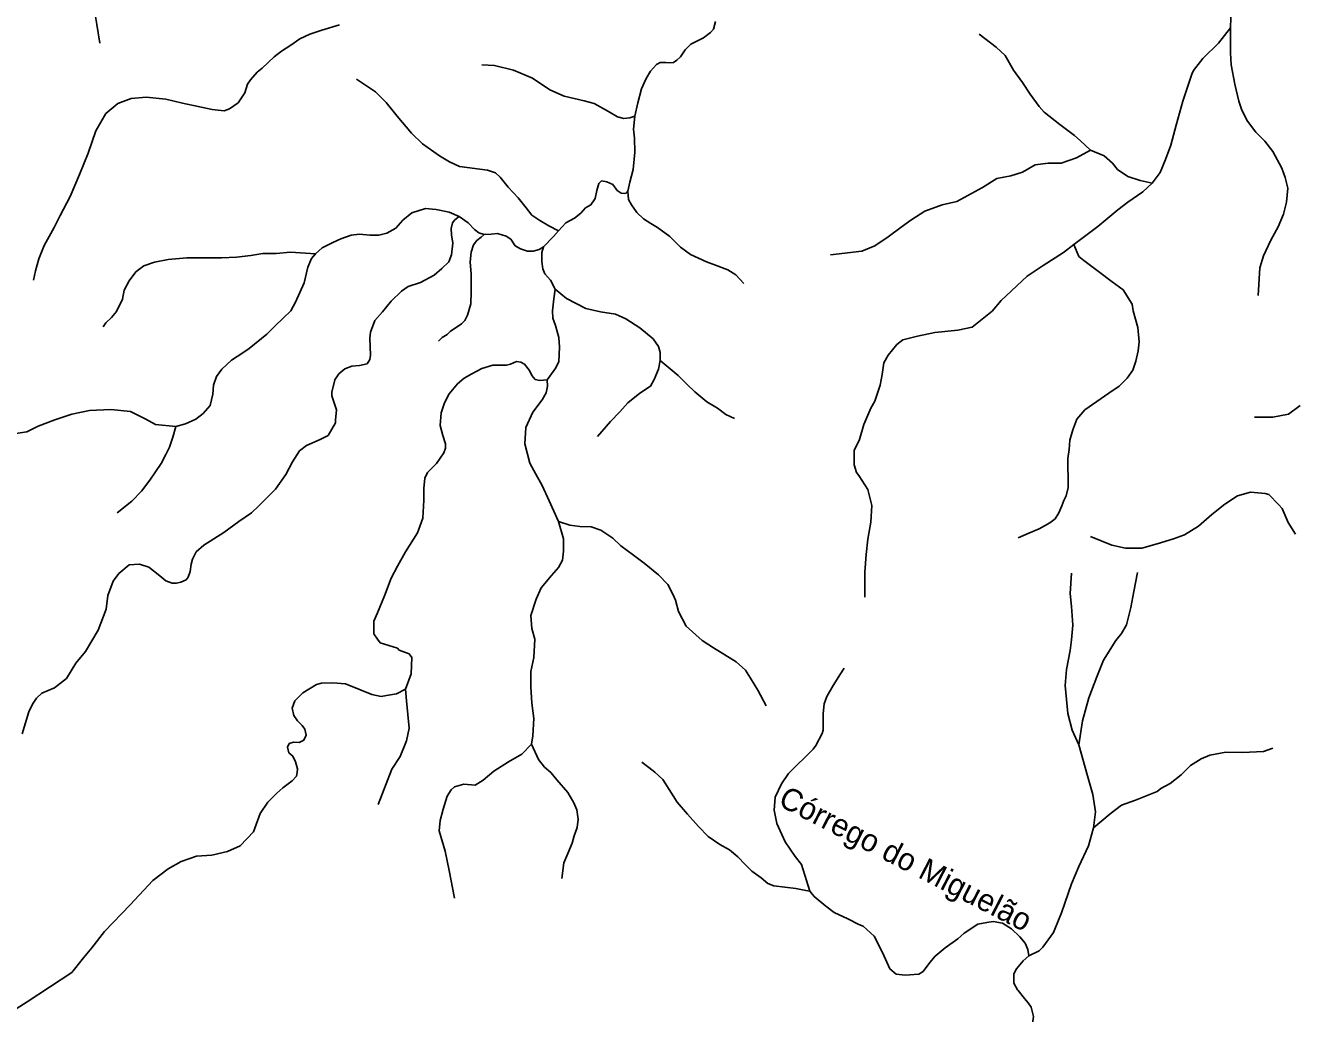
# Model space of a CAD drawing. Extents: x 436.3 to 500.4, y 8231 to 8286.4.
# Drawn here: x 456.78 to 465.31, y 8261.09 to 8267.74 of the extents above; entities that cross this region are included whole.
import ezdxf

# ---------------------------------------------------------------- set-up
doc = ezdxf.new("R2010")
doc.units = 0
doc.header["$LTSCALE"] = 0.08
doc.linetypes.add('LONG_DASHED', pattern=[7.5, 6, -1.5])
doc.layers.add('61', color=7, linetype='Continuous')
doc.layers.add('9', color=7, linetype='LONG_DASHED', lineweight=25)

msp = doc.modelspace()

# ---------------------------------------------------------------- linework, layer by layer
at = {"layer": '9'}
for points in [[(457.2814, 8267.6213), (457.2633, 8267.7468), (457.2498, 8267.8274), (457.2318, 8267.9082), (457.2093, 8268.1056), (457.1867, 8268.2042), (457.1732, 8268.2671), (457.1777, 8268.3343), (457.1957, 8268.4062), (457.2362, 8268.5453), (457.2497, 8268.6082), (457.2451, 8268.6844), (457.2361, 8268.7473), (457.1956, 8268.8372), (457.1595, 8268.9135), (457.1053, 8269.0054), (457.0783, 8269.0818), (457.0468, 8269.1671), (457.0287, 8269.2526), (457.0287, 8269.3694), (457.03, 8269.4566)], [(464.8947, 8267.7236), (464.8968, 8267.7915), (464.9249, 8267.9547), (464.9529, 8268.074), (464.9928, 8268.1576), (465.0567, 8268.2651), (465.1087, 8268.3568), (465.185, 8268.4466)], [(460.8851, 8267.1303), (460.9041, 8267.2198), (460.9298, 8267.3138), (460.9614, 8267.3834), (460.99, 8267.4318), (461.0299, 8267.4774), (461.0557, 8267.4917), (461.0928, 8267.4918), (461.1185, 8267.4889), (461.1442, 8267.4918), (461.167, 8267.506), (461.1928, 8267.5288), (461.2242, 8267.5773), (461.2613, 8267.6144), (461.347, 8267.6572), (461.393, 8267.6927), (461.413, 8267.7155), (461.4274, 8267.7668)], [(456.8355, 8266.026), (456.849, 8266.0887), (456.8715, 8266.1692), (456.9074, 8266.2588), (456.975, 8266.3796), (457.0154, 8266.4603), (457.0829, 8266.59), (457.146, 8266.7378), (457.2044, 8266.8811), (457.2549, 8267.0304), (457.3224, 8267.1469), (457.4035, 8267.2142), (457.4938, 8267.2491), (457.594, 8267.2585), (457.7274, 8267.2452), (457.8399, 8267.2183), (457.9435, 8267.1958), (458.0385, 8267.1741), (458.1195, 8267.1651), (458.1555, 8267.1784), (458.214, 8267.2188), (458.259, 8267.286), (458.277, 8267.3444), (458.2972, 8267.3739), (458.3411, 8267.4261), (458.376, 8267.4519), (458.457, 8267.5281), (458.5065, 8267.5684), (458.5695, 8267.6088), (458.628, 8267.6492), (458.6971, 8267.6813), (458.7781, 8267.7082), (458.8951, 8267.7441)], [(463.2016, 8267.682), (463.3181, 8267.5937), (463.3787, 8267.5379), (463.4345, 8267.4402), (463.4951, 8267.3565), (463.5464, 8267.2774), (463.6069, 8267.1937), (463.6395, 8267.1565), (463.7467, 8267.0729), (463.8446, 8266.9985), (463.8818, 8266.9659), (463.9528, 8266.9006)], [(464.3685, 8266.6777), (464.4215, 8266.7506), (464.4574, 8266.838), (464.4933, 8266.9335), (464.5293, 8267.0687), (464.5733, 8267.2317), (464.6334, 8267.4135), (464.6454, 8267.4374), (464.7092, 8267.517), (464.813, 8267.6204), (464.8947, 8267.7236)], [(465.0805, 8265.9223), (465.0928, 8266.1091), (465.1173, 8266.1903), (465.1662, 8266.2959), (465.2151, 8266.3852), (465.2518, 8266.4705), (465.2722, 8266.5518), (465.2804, 8266.6451), (465.2639, 8266.7159), (465.2399, 8266.7792), (465.1789, 8266.8929), (465.1261, 8266.962), (465.0652, 8267.0229), (465.0083, 8267.096), (464.9717, 8267.1691), (464.9512, 8267.2311), (464.9229, 8267.3449), (464.8986, 8267.4749), (464.8945, 8267.557), (464.8947, 8267.7236)], [(459.8554, 8267.4759), (459.9406, 8267.47), (460.0683, 8267.4397), (460.1961, 8267.3852), (460.3116, 8267.3065), (460.4089, 8267.2641), (460.5427, 8267.2339), (460.6096, 8267.2158), (460.7069, 8267.1614), (460.7677, 8267.125), (460.8103, 8267.113), (460.8515, 8267.1185), (460.8851, 8267.1303)], [(459.0101, 8267.3789), (459.1377, 8267.294), (459.2107, 8267.2213), (459.2838, 8267.1304), (459.381, 8267.0152), (459.454, 8266.9425), (459.5695, 8266.8638), (459.6365, 8266.8214), (459.7034, 8266.7911), (459.8919, 8266.7669), (459.9466, 8266.7487), (459.977, 8266.7185), (460.0318, 8266.6518), (460.0986, 8266.5792), (460.1534, 8266.5125), (460.1899, 8266.4641), (460.2445, 8266.4277), (460.3054, 8266.3915), (460.3698, 8266.358)], [(460.8383, 8266.6251), (460.8498, 8266.6848), (460.8726, 8266.7702), (460.884, 8266.8868), (460.8812, 8266.9807), (460.8756, 8267.0433), (460.8851, 8267.1303)], [(462.2021, 8266.1965), (462.412, 8266.2201), (462.5006, 8266.2575), (462.5893, 8266.318), (462.678, 8266.3832), (462.7433, 8266.4298), (462.8367, 8266.4904), (462.9534, 8266.5324), (463.0513, 8266.5558), (463.224, 8266.649), (463.322, 8266.7096), (463.4153, 8266.7282), (463.4945, 8266.7517), (463.5786, 8266.8029), (463.6672, 8266.8123), (463.7557, 8266.8123), (463.8584, 8266.8496), (463.9528, 8266.9006)], [(463.9528, 8266.9006), (464.045, 8266.8637), (464.1009, 8266.8126), (464.1335, 8266.7707), (464.2033, 8266.7243), (464.2873, 8266.6964), (464.3685, 8266.6777)], [(460.3698, 8266.358), (460.42, 8266.4118), (460.4775, 8266.444), (460.5207, 8266.4762), (460.553, 8266.5121), (460.589, 8266.5335), (460.6177, 8266.5765), (460.6285, 8266.6302), (460.6429, 8266.6767), (460.6608, 8266.6947), (460.6967, 8266.6876), (460.7362, 8266.6696), (460.765, 8266.6303), (460.7926, 8266.6108), (460.8126, 8266.608), (460.8269, 8266.6108), (460.8383, 8266.6251)], [(463.8405, 8266.2653), (464.0012, 8266.3867), (464.1368, 8266.4981), (464.2046, 8266.5498), (464.3043, 8266.6213), (464.3685, 8266.6777)], [(461.6189, 8266.0042), (461.5634, 8266.0627), (461.5112, 8266.0952), (461.4264, 8266.1276), (461.3676, 8266.1502), (461.2599, 8266.199), (461.1913, 8266.2476), (461.1195, 8266.3192), (461.0379, 8266.3809), (460.9922, 8266.4069), (460.9433, 8266.4393), (460.8976, 8266.4817), (460.8616, 8266.5337), (460.842, 8266.5694), (460.8383, 8266.6251)], [(458.7334, 8266.2036), (458.7801, 8266.2429), (458.852, 8266.2786), (458.9058, 8266.3036), (458.9741, 8266.3287), (459.0315, 8266.3357), (459.0998, 8266.3286), (459.1609, 8266.3286), (459.2147, 8266.3428), (459.2758, 8266.375), (459.3225, 8266.4287), (459.382, 8266.4795), (459.4755, 8266.5081), (459.5472, 8266.5009), (459.6335, 8266.4831), (459.7018, 8266.4544)], [(459.7018, 8266.4544), (459.673, 8266.4312), (459.6569, 8266.4118), (459.6472, 8266.3733), (459.6504, 8266.3317), (459.6601, 8266.2739), (459.6504, 8266.1969), (459.6311, 8266.1488), (459.586, 8266.1038), (459.5344, 8266.0589), (459.441, 8266.0109), (459.3573, 8265.982), (459.313, 8265.952), (459.2439, 8265.8833), (459.186, 8265.8124), (459.1341, 8265.7552), (459.1053, 8265.6749), (459.0996, 8265.6348), (459.1053, 8265.5202), (459.0996, 8265.4915), (459.0824, 8265.4629), (459.0306, 8265.4514), (458.9788, 8265.4457), (458.9328, 8265.4286), (458.8925, 8265.3942), (458.8637, 8265.3541), (458.8436, 8265.2723), (458.8436, 8265.2473), (458.8752, 8265.1534), (458.8682, 8265.0831), (458.8682, 8265.0659), (458.8192, 8264.9809), (458.7667, 8264.952), (458.6746, 8264.9121), (458.6266, 8264.8769), (458.5805, 8264.8024), (458.5346, 8264.7165), (458.4655, 8264.6191), (458.3504, 8264.5045), (458.3043, 8264.4587), (458.218, 8264.4015), (458.118, 8264.326), (457.9831, 8264.2414), (457.9312, 8264.196), (457.9063, 8264.1483), (457.898, 8264.1132), (457.8897, 8264.0636), (457.8763, 8264.0258), (457.8638, 8264.0093), (457.8275, 8263.9932), (457.7984, 8263.985), (457.7693, 8263.9851), (457.7277, 8264.0017), (457.6862, 8264.035), (457.6116, 8264.0932), (457.549, 8264.1139), (457.4802, 8264.109), (457.4112, 8264.0518), (457.3728, 8263.9986), (457.3364, 8263.9027), (457.325, 8263.8109), (457.2715, 8263.6704), (457.1851, 8263.527), (457.1218, 8263.4468), (457.0585, 8263.3434), (456.978, 8263.2805), (456.8916, 8263.2462), (456.8571, 8263.2118), (456.8283, 8263.1716), (456.8053, 8263.1198), (456.7881, 8263.0682), (456.7593, 8262.9705)], [(459.7018, 8266.4544), (459.7628, 8266.4115), (459.8052, 8266.3672), (459.8343, 8266.3448), (459.8708, 8266.3325)], [(459.5617, 8265.6152), (459.5871, 8265.6406), (459.6199, 8265.6588), (459.6417, 8265.6805), (459.718, 8265.7312), (459.7399, 8265.7534), (459.7581, 8265.7897), (459.78, 8265.8658), (459.7836, 8265.9455), (459.7836, 8266.065), (459.7763, 8266.1485), (459.7836, 8266.2137), (459.7982, 8266.2644), (459.82, 8266.2934), (459.8491, 8266.3151), (459.8708, 8266.3325)], [(459.8708, 8266.3325), (459.9172, 8266.3364), (459.9603, 8266.34), (460.0178, 8266.3221), (460.0501, 8266.3006), (460.0788, 8266.2577), (460.1148, 8266.2363), (460.1615, 8266.2219), (460.201, 8266.2219), (460.2405, 8266.2327), (460.2706, 8266.2496)], [(460.2706, 8266.2496), (460.3375, 8266.3186), (460.3698, 8266.358)], [(460.347, 8265.9655), (460.316, 8266.0261), (460.2791, 8266.0685), (460.2649, 8266.1025), (460.2592, 8266.1506), (460.2592, 8266.2128), (460.2706, 8266.2496)], [(462.4332, 8263.8924), (462.4332, 8264.0595), (462.4412, 8264.1788), (462.4532, 8264.2822), (462.473, 8264.3976), (462.481, 8264.5089), (462.4532, 8264.6162), (462.3934, 8264.7116), (462.3775, 8264.7314), (462.3615, 8264.783), (462.3615, 8264.8784), (462.3974, 8264.954), (462.4253, 8265.0534), (462.4732, 8265.1632), (462.5011, 8265.2109), (462.537, 8265.3182), (462.549, 8265.3898), (462.561, 8265.4693), (462.5889, 8265.521), (462.6487, 8265.5926), (462.6886, 8265.6244), (462.7882, 8265.6484), (462.9038, 8265.6724), (463.0592, 8265.6886), (463.1549, 8265.7085), (463.2905, 8265.8159), (463.3514, 8265.8895), (463.5268, 8266.0526), (463.6344, 8266.1242), (463.77, 8266.2118), (463.8405, 8266.2653)], [(463.4663, 8264.2912), (463.5368, 8264.3215), (463.6074, 8264.3517), (463.678, 8264.3921), (463.7149, 8264.419), (463.7385, 8264.4592), (463.7587, 8264.5062), (463.7721, 8264.5431), (463.7889, 8264.5732), (463.8023, 8264.6302), (463.8023, 8264.7039), (463.7991, 8264.7609), (463.7991, 8264.8246), (463.8092, 8264.885), (463.8125, 8264.9486), (463.8327, 8265.019), (463.8597, 8265.0894), (463.9134, 8265.1531), (464.0752, 8265.2652), (464.1458, 8265.3122), (464.1996, 8265.3659), (464.2365, 8265.4195), (464.2567, 8265.4798), (464.2736, 8265.5502), (464.2804, 8265.6105), (464.2703, 8265.7077), (464.24, 8265.8198), (464.2334, 8265.8634), (464.1729, 8265.9605), (464.0991, 8266.0141), (464.005, 8266.0845), (463.9076, 8266.1582), (463.8741, 8266.1849), (463.8405, 8266.2653)], [(457.305, 8265.7122), (457.3235, 8265.7381), (457.3606, 8265.775), (457.394, 8265.8155), (457.4348, 8265.8967), (457.4459, 8265.9594), (457.4793, 8266.0222), (457.5238, 8266.0812), (457.5795, 8266.1218), (457.65, 8266.1475), (457.7427, 8266.1659), (457.8688, 8266.1769), (458.0136, 8266.1767), (458.1025, 8266.1766), (458.2028, 8266.1802), (458.2992, 8266.1912), (458.3808, 8266.206), (458.4698, 8266.2059), (458.5663, 8266.2132), (458.7334, 8266.2036)], [(457.7952, 8265.0411), (457.8602, 8265.0575), (457.9284, 8265.0895), (457.9787, 8265.1288), (458.0253, 8265.1825), (458.0433, 8265.2576), (458.0469, 8265.3184), (458.0689, 8265.3764), (458.1048, 8265.4264), (458.1694, 8265.4872), (458.2449, 8265.5371), (458.288, 8265.5656), (458.4065, 8265.6621), (458.4639, 8265.7193), (458.5178, 8265.7692), (458.5681, 8265.8193), (458.6004, 8265.8765), (458.6579, 8266.0087), (458.6832, 8266.1142), (458.7084, 8266.1714), (458.7334, 8266.2036)], [(460.294, 8265.355), (460.3129, 8265.3787), (460.3527, 8265.4353), (460.3726, 8265.4778), (460.3782, 8265.5751), (460.3725, 8265.6402), (460.3498, 8265.7194), (460.3328, 8265.7703), (460.3299, 8265.8184), (460.3385, 8265.9005), (460.347, 8265.9655)], [(461.0551, 8265.4839), (461.0551, 8265.5377), (461.0438, 8265.5801), (461.0068, 8265.631), (460.9189, 8265.7045), (460.8244, 8265.7648), (460.7534, 8265.7959), (460.6541, 8265.8127), (460.5547, 8265.8353), (460.4241, 8265.9031), (460.347, 8265.9655)], [(459.7343, 8265.3653), (459.7865, 8265.3948), (459.855, 8265.4309), (459.9277, 8265.4527), (460.0197, 8265.454), (460.0471, 8265.4592), (460.0869, 8265.4772), (460.117, 8265.4746), (460.1417, 8265.4592), (460.1747, 8265.4167), (460.1911, 8265.3845), (460.2144, 8265.3575), (460.2446, 8265.3498), (460.294, 8265.355)], [(460.632, 8264.9741), (460.7201, 8265.0734), (460.7825, 8265.1384), (460.8365, 8265.2007), (460.9188, 8265.2659), (460.9898, 8265.3112), (461.0153, 8265.3565), (461.0438, 8265.4273), (461.0551, 8265.4839)], [(461.5546, 8265.094), (461.4978, 8265.1222), (461.4411, 8265.1646), (461.3702, 8265.2069), (461.2878, 8265.2747), (461.2339, 8265.3256), (461.1772, 8265.385), (461.0551, 8265.4839)], [(459.3408, 8263.2718), (459.3775, 8263.3765), (459.3836, 8263.4865), (459.3652, 8263.5109), (459.298, 8263.5354), (459.2858, 8263.5476), (459.1696, 8263.5844), (459.1512, 8263.6088), (459.1267, 8263.6455), (459.1267, 8263.6821), (459.1267, 8263.731), (459.1512, 8263.7859), (459.2001, 8263.9017), (459.2431, 8264.0201), (459.286, 8264.0993), (459.3409, 8264.1969), (459.4205, 8264.3249), (459.4571, 8264.4225), (459.4632, 8264.5445), (459.4632, 8264.6237), (459.4696, 8264.6933), (459.4879, 8264.7298), (459.5491, 8264.7908), (459.598, 8264.8639), (459.6102, 8264.8944), (459.6102, 8264.9248), (459.5919, 8264.9798), (459.5735, 8265.0468), (459.5796, 8265.1321), (459.6041, 8265.1991), (459.6347, 8265.2601), (459.6897, 8265.3271), (459.7343, 8265.3653)], [(460.3705, 8264.4004), (460.3082, 8264.5406), (460.26, 8264.6435), (460.2188, 8264.7188), (460.1776, 8264.7942), (460.1432, 8264.9245), (460.1501, 8265.0341), (460.1982, 8265.1368), (460.26, 8265.2191), (460.2875, 8265.2671), (460.2969, 8265.3122), (460.294, 8265.355)], [(455.8196, 8264.6986), (455.9176, 8264.7495), (456.0179, 8264.7681), (456.1183, 8264.7993), (456.2249, 8264.8492), (456.3252, 8264.9177), (456.4192, 8264.9675), (456.5321, 8264.9985), (456.6136, 8264.9922), (456.7168, 8264.993), (456.7921, 8265.0053), (456.8673, 8265.0427), (456.9801, 8265.0861), (457.093, 8265.1234), (457.2121, 8265.1482), (457.3563, 8265.1542), (457.488, 8265.1415), (457.5883, 8265.0914), (457.6573, 8265.0538), (457.7952, 8265.0411)], [(465.0574, 8265.1045), (465.1809, 8265.1044), (465.2851, 8265.1238), (465.3632, 8265.1823)], [(457.3991, 8264.4589), (457.4989, 8264.5369), (457.5631, 8264.6042), (457.6201, 8264.6787), (457.695, 8264.7922), (457.727, 8264.8524), (457.7519, 8264.9021), (457.7733, 8264.9695), (457.7952, 8265.0411)], [(463.953, 8264.2996), (464.0967, 8264.2424), (464.187, 8264.2218), (464.2979, 8264.2219), (464.4006, 8264.2506), (464.5115, 8264.2833), (464.5854, 8264.312), (464.6798, 8264.3693), (464.7702, 8264.4472), (464.8563, 8264.5168), (464.9426, 8264.5741), (465.0288, 8264.5986), (465.1273, 8264.5903), (465.1519, 8264.5821), (465.2176, 8264.5166), (465.2422, 8264.4878), (465.2832, 8264.3936), (465.3326, 8264.3157)], [(460.1882, 8262.901), (460.1983, 8262.9577), (460.2052, 8263.0744), (460.1915, 8263.1775), (460.1846, 8263.2873), (460.1846, 8263.3903), (460.2052, 8263.4864), (460.2121, 8263.6098), (460.1918, 8263.6801), (460.1849, 8263.7693), (460.2193, 8263.8792), (460.2536, 8263.9545), (460.3224, 8264.0369), (460.3705, 8264.0918), (460.398, 8264.1399), (460.4049, 8264.2015), (460.4049, 8264.2838), (460.3705, 8264.4004)], [(461.7682, 8263.1599), (461.7133, 8263.2657), (461.6621, 8263.3459), (461.6293, 8263.4007), (461.5671, 8263.4554), (461.4136, 8263.55), (461.3367, 8263.601), (461.2307, 8263.6957), (461.1795, 8263.7942), (461.1576, 8263.8709), (461.1393, 8263.911), (461.1064, 8263.9767), (461.0443, 8264.0423), (460.9482, 8264.1206), (460.8751, 8264.1752), (460.7911, 8264.2371), (460.7362, 8264.2882), (460.6558, 8264.3428), (460.59, 8264.3647), (460.5131, 8264.3683), (460.4474, 8264.3755), (460.3705, 8264.4004)], [(463.8245, 8264.0529), (463.8147, 8263.9166), (463.8245, 8263.829), (463.8343, 8263.7024), (463.8245, 8263.6049), (463.8148, 8263.5319), (463.7904, 8263.4051), (463.7808, 8263.298), (463.8004, 8263.108), (463.8297, 8262.9959), (463.8739, 8262.8973)], [(464.2685, 8264.0568), (464.2441, 8263.9302), (464.2247, 8263.8231), (464.1955, 8263.7062), (464.1613, 8263.6478), (464.1223, 8263.599), (464.0395, 8263.4675), (463.9956, 8263.3554), (463.942, 8263.2141), (463.8982, 8263.0581), (463.8739, 8262.8973)], [(462.2933, 8263.4133), (462.2688, 8263.3765), (462.2199, 8263.297), (462.1771, 8263.2236), (462.1587, 8263.1747), (462.1526, 8263.1074), (462.1526, 8262.9973), (462.1465, 8262.973), (462.1037, 8262.8933), (462.0853, 8262.8688), (461.9201, 8262.7035), (461.8711, 8262.6361), (461.8284, 8262.5443), (461.8222, 8262.4587), (461.8406, 8262.367), (461.8957, 8262.2441), (461.9631, 8262.1464), (462.006, 8262.0914), (462.0633, 8261.9118)], [(456.6706, 8261.0882), (456.793, 8261.1675), (457.0936, 8261.3654), (457.1732, 8261.463), (457.2282, 8261.5301), (457.3138, 8261.64), (457.4868, 8261.8194), (457.6397, 8261.9842), (457.7436, 8262.0634), (457.8293, 8262.1121), (457.9332, 8262.1485), (458.0372, 8262.1545), (458.1411, 8262.1786), (458.2281, 8262.217), (458.3174, 8262.3116), (458.3613, 8262.4349), (458.4125, 8262.5106), (458.4739, 8262.5715), (458.5152, 8262.607), (458.5763, 8262.6558), (458.6069, 8262.6863), (458.6114, 8262.711), (458.6131, 8262.7352), (458.6008, 8262.7841), (458.5825, 8262.8208), (458.5545, 8262.8436), (458.5457, 8262.882), (458.558, 8262.9064), (458.587, 8262.9165), (458.6253, 8262.9132), (458.6555, 8262.9301), (458.6717, 8262.9622), (458.662, 8263.004), (458.6437, 8263.0284), (458.6131, 8263.059), (458.5886, 8263.0958), (458.5763, 8263.1446), (458.5947, 8263.1935), (458.6498, 8263.2483), (458.7415, 8263.3031), (458.7749, 8263.3123), (458.8515, 8263.3151), (458.9371, 8263.3089), (459.0412, 8263.266), (459.1145, 8263.2354), (459.1757, 8263.2231), (459.2124, 8263.2291), (459.2796, 8263.2413), (459.3408, 8263.2718)], [(459.1573, 8262.496), (459.2491, 8262.7343), (459.3041, 8262.8198), (459.347, 8262.9236), (459.3653, 8263.0091), (459.347, 8263.1934), (459.3408, 8263.2718)], [(459.6692, 8261.8656), (459.6348, 8262.0511), (459.6073, 8262.1817), (459.566, 8262.3192), (459.5729, 8262.3879), (459.5935, 8262.4634), (459.621, 8262.5527), (459.6485, 8262.5939), (459.6692, 8262.6145), (459.7341, 8262.6325), (459.8099, 8262.6253), (459.8622, 8262.659), (459.9355, 8262.7212), (460.0345, 8262.7834), (460.1247, 8262.8356), (460.1882, 8262.901)], [(460.392, 8261.9984), (460.406, 8262.1033), (460.4339, 8262.1662), (460.4619, 8262.2362), (460.4759, 8262.2851), (460.497, 8262.3411), (460.504, 8262.397), (460.4943, 8262.4598), (460.4741, 8262.5067), (460.4338, 8262.5772), (460.3598, 8262.6611), (460.3196, 8262.7114), (460.2759, 8262.7483), (460.2355, 8262.7986), (460.1882, 8262.901)], [(463.8739, 8262.8973), (463.9325, 8262.6879), (463.9672, 8262.563), (463.9868, 8262.4462), (463.9723, 8262.339)], [(465.1808, 8262.8762), (465.1174, 8262.8519), (464.976, 8262.847), (464.8639, 8262.8471), (464.7567, 8262.8276), (464.6982, 8262.8033), (464.6251, 8262.7594), (464.5617, 8262.6961), (464.4886, 8262.6375), (464.4253, 8262.6035), (464.4009, 8262.584), (464.2547, 8262.5255), (464.162, 8262.4913), (464.084, 8262.4328), (463.9723, 8262.339)], [(460.932, 8262.7818), (460.9779, 8262.7457), (461.019, 8262.7144), (461.0721, 8262.6638), (461.1155, 8262.5963), (461.1687, 8262.5119), (461.2388, 8262.4299), (461.3136, 8262.3481), (461.3789, 8262.2807), (461.4562, 8262.2277), (461.5214, 8262.1917), (461.5769, 8262.1435), (461.6277, 8262.0929), (461.6711, 8262.0472), (461.7348, 8262.0028), (461.7807, 8261.9643), (461.8205, 8261.9493), (461.8933, 8261.9399), (461.9691, 8261.931), (462.0367, 8261.9166), (462.0633, 8261.9118)], [(463.9723, 8262.339), (463.9382, 8262.2171), (463.8739, 8262.0787), (463.8251, 8261.9618), (463.7569, 8261.7668), (463.7424, 8261.7278), (463.7034, 8261.6352), (463.6305, 8261.5363), (463.6061, 8261.5119), (463.5367, 8261.4765)], [(462.0633, 8261.9118), (462.0918, 8261.8776), (462.1713, 8261.8105), (462.2265, 8261.7679), (462.3184, 8261.7253), (462.3918, 8261.6888), (462.4224, 8261.6766), (462.496, 8261.6095), (462.5511, 8261.4992), (462.6002, 8261.3893), (462.643, 8261.3527), (462.7043, 8261.3468), (462.7961, 8261.3531), (462.8266, 8261.3715), (462.8695, 8261.4327), (462.9062, 8261.4756), (462.9735, 8261.5307), (463.0592, 8261.592), (463.102, 8261.6288), (463.1938, 8261.69), (463.2549, 8261.7023), (463.2978, 8261.7085), (463.359, 8261.6964), (463.4202, 8261.6599), (463.4754, 8261.6049), (463.5122, 8261.5623), (463.5311, 8261.5191), (463.5367, 8261.4765)], [(463.5367, 8261.4765), (463.4988, 8261.4435), (463.4549, 8261.3898), (463.4355, 8261.3557), (463.4355, 8261.2924), (463.46, 8261.2487), (463.4649, 8261.2438), (463.5087, 8261.1902), (463.5331, 8261.1611), (463.5528, 8261.1319), (463.5674, 8261.0687), (463.5498, 8260.9386)]]:
    msp.add_lwpolyline(points, dxfattribs=at)

# ---------------------------------------------------------------- texts
at = {"layer": '61'}
msp.add_text('Córrego do Miguelão', height=0.15, rotation=332.758, dxfattribs=at).set_placement((461.8418, 8262.4935))

doc.saveas('drawing.dxf')
